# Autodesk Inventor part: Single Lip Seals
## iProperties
Company: Engineering Services Northland (1988) Ltd
Title: Single Lip Seals
Author: Malcolm Mack
Shininess: 60.0
PropertySet Name: _Private Model Information
Created: 2000-12
Part Number: 25x47x10
Material: Steel, Mild
Description: Single Lip Seal
Document SubType Name: Modeling
Designer: Malcolm Mack
Control State: 0
Master: False
Checked Out: False
PropertySet Name: Design Tracking Control
Density: 0.0
Volumn: 0.0
Area: 0.0
PropertySet Name: Model Information
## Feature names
1. Revolution6
